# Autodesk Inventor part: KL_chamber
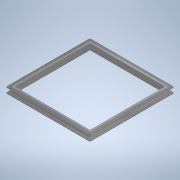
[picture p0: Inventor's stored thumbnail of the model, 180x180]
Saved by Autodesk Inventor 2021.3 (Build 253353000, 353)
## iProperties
Created: 2015-01
Part Number: KL_chamber
Material: アルミニウム 6061
Document SubType Name: Modeling
Designer: jh
Density: 2.71 g/cm^3
Appearance: アルミニウム - フラット
Mass: 47149.2 g
Surface Area: 21283 cm^2
Volume: 17398.2 cm^3
Author: jh
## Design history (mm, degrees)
sketch "Sketch4"
  geometry: L1 (-665, 665)-(665, 665); L2 (665, 665)-(665, -665); L3 (665, -665)-(-665, -665); L4 (-665, -665)-(-665, 665); L5 (-665, 665)-(665, -665); L6 (665, 665)-(-665, -665); 1 further point
  constraints: 12 end point, 2 midpoint, 2 parallel, 1 horizontal, 1 perpendicular
  dimensions: "d12" = 1330 distance of L2.end L3.end; "d13" = 1330 distance of L1.end L2.end
extrude "Extrusion4" new body sketch "Sketch4" distance "d14" = 10; taper "d15" = 0 deg
sketch "Sketch5"
  geometry: L1 (-592.75, 592.75)-(592.75, 592.75); L2 (592.75, 592.75)-(592.75, -592.75); L3 (592.75, -592.75)-(-592.75, -592.75); L4 (-592.75, -592.75)-(-592.75, 592.75); L5 (-592.75, 592.75)-(592.75, -592.75); L6 (592.75, 592.75)-(-592.75, -592.75); 1 further point
  constraints: 12 end point, 2 midpoint, 2 parallel, 1 horizontal, 1 perpendicular
  dimensions: "d16" = 1185.5 distance of L2.end L3.end; "d17" = 1185.5 distance of L1.end L2.end
extrude "Extrusion5" cut sketch "Sketch5" distance "d18" = 167.5; taper "d19" = 0 deg
sketch "Sketch6"
  geometry: L1 (-620, 620)-(620, 620); L2 (620, 620)-(620, -620); L3 (620, -620)-(-620, -620); L4 (-620, -620)-(-620, 620); L5 (-620, 620)-(620, -620); L6 (620, 620)-(-620, -620); 1 further point
  constraints: 12 end point, 2 midpoint, 2 parallel, 1 horizontal, 1 perpendicular
  dimensions: "d20" = 1240 distance of L2.end L3.end; "d21" = 1240 distance of L1.end L2.end
extrude "Extrusion6" join sketch "Sketch6" distance "d22" = 70; taper "d23" = 0 deg
sketch "Sketch7"
  geometry: L1 (-592.75, 592.75)-(592.75, 592.75); L2 (592.75, 592.75)-(592.75, -592.75); L3 (592.75, -592.75)-(-592.75, -592.75); L4 (-592.75, -592.75)-(-592.75, 592.75); L5 (-592.75, 592.75)-(592.75, -592.75); L6 (592.75, 592.75)-(-592.75, -592.75); 1 further point
  constraints: 12 end point, 2 midpoint, 2 parallel, 1 horizontal, 1 perpendicular
  dimensions: "d24" = 1185.5 distance of L2.end L3.end; "d25" = 1185.5 distance of L1.end L2.end
extrude "Extrusion7" cut sketch "Sketch7" distance "d26" = 445.75; taper "d27" = 0 deg
sketch "Sketch8"
  geometry: L1 (-665, 665)-(665, 665); L2 (665, 665)-(665, -665); L3 (665, -665)-(-665, -665); L4 (-665, -665)-(-665, 665); L5 (-665, 665)-(665, -665); L6 (665, 665)-(-665, -665); 1 further point
  constraints: 12 end point, 2 midpoint, 2 parallel, 1 horizontal, 1 perpendicular
  dimensions: "d28" = 1330 distance of L2.end L3.end; "d29" = 1330 distance of L1.end L2.end
extrude "Extrusion8" join sketch "Sketch8" distance "d30" = 10; taper "d31" = 0 deg
sketch "Sketch9"
  geometry: L1 (-592.75, 592.75)-(592.75, 592.75); L2 (592.75, 592.75)-(592.75, -592.75); L3 (592.75, -592.75)-(-592.75, -592.75); L4 (-592.75, -592.75)-(-592.75, 592.75); L5 (-592.75, 592.75)-(592.75, -592.75); L6 (592.75, 592.75)-(-592.75, -592.75); 1 further point
  constraints: 12 end point, 2 midpoint, 2 parallel, 1 horizontal, 1 perpendicular
  dimensions: "d32" = 1185.5 distance of L2.end L3.end; "d33" = 1185.5 distance of L1.end L2.end
extrude "Extrusion9" cut sketch "Sketch9" distance "d34" = 271.25; taper "d35" = 0 deg
sketch "Sketch10"
  geometry: L1 (-622.75, 622.75)-(622.75, 622.75); L2 (622.75, 622.75)-(622.75, -622.75); L3 (622.75, -622.75)-(-622.75, -622.75); L4 (-622.75, -622.75)-(-622.75, 622.75); L5 (-622.75, 622.75)-(622.75, -622.75); L6 (622.75, 622.75)-(-622.75, -622.75); 1 further point
  constraints: 12 end point, 2 midpoint, 2 parallel, 1 horizontal, 1 perpendicular
  dimensions: "d36" = 1245.5 distance of L2.end L3.end; "d37" = 1245.5 distance of L1.end L2.end
extrude "Extrusion10" join sketch "Sketch10" distance "d38" = 3; taper "d39" = 0 deg
sketch "Sketch11"
  geometry: L1 (-622.75, 622.75)-(622.75, 622.75); L2 (622.75, 622.75)-(622.75, -622.75); L3 (622.75, -622.75)-(-622.75, -622.75); L4 (-622.75, -622.75)-(-622.75, 622.75); L5 (-622.75, 622.75)-(622.75, -622.75); L6 (622.75, 622.75)-(-622.75, -622.75); 1 further point
  constraints: 12 end point, 2 midpoint, 2 parallel, 1 horizontal, 1 perpendicular
  dimensions: "d40" = 1245.5 distance of L2.end L3.end; "d41" = 1245.5 distance of L1.end L2.end
extrude "Extrusion11" join sketch "Sketch11" distance "d42" = 3; taper "d43" = 0 deg
sketch "Sketch12"
  geometry: L1 (-592.75, 592.75)-(592.75, 592.75); L2 (592.75, 592.75)-(592.75, -592.75); L3 (592.75, -592.75)-(-592.75, -592.75); L4 (-592.75, -592.75)-(-592.75, 592.75); L5 (-592.75, 592.75)-(592.75, -592.75); L6 (592.75, 592.75)-(-592.75, -592.75); 1 further point
  constraints: 12 end point, 2 midpoint, 2 parallel, 1 horizontal, 1 perpendicular
  dimensions: "d44" = 1185.5 distance of L2.end L3.end; "d45" = 1185.5 distance of L1.end L2.end
extrude "Extrusion12" cut sketch "Sketch12" distance "d46" = 429.25; taper "d47" = 0 deg
fillet "フィレット1" dims "d48" = 20
sketch "スケッチ13"
  geometry: L1 (665, -645)-(665, 645) reference; L2 (645, 665)-(-645, 665) reference; 3 further points
  dimensions: "d49" = 20 distance from line of L1 point (645, 645); "d50" = 20 distance from line of L2 point (645, 645); "d53" = 1290 distance of point (645, 645) point (-645, 645)
hole "穴1" sketch "スケッチ13" at (645, 645), (-645, 645) diameter "d59" = 6; stored, may be unused: countersink angle "d63" = 90 deg, drill point angle "d65" = 118 deg; dims "d60" = 100, "d61" = 4, "d62" = 2, "d64" = 100
sketch "スケッチ14"
  geometry: L1 (-645, -665)-(645, -665) reference; L2 (-665, 645)-(-665, -645) reference; 37 further points
  constraints: 1 horizontal, 1 vertical, 35 other
  dimensions: "d66" = 53 distance from line of L1 point (-650, -612); "d67" = 15 distance from line of L2 point (-650, -612); "d70" = 1300 distance of point (-650, -612) point (650, -612); "d73" = 72 distance of point (-650, -612) point (-650, -540)
hole "穴2" sketch "スケッチ14" diameter "d76" = 3.2; stored, may be unused: countersink angle "d80" = 90 deg, drill point angle "d82" = 118 deg; dims "d77" = 100, "d78" = 4, "d79" = 2, "d81" = 100
sketch "スケッチ15"
  geometry: L1 (-645, -665)-(645, -665) reference; L2 (-665, 645)-(-665, -645) reference; 37 further points
  constraints: 1 horizontal, 1 vertical, 35 other
  dimensions: "d83" = 15 distance from line of L1 point (-612, -650); "d84" = 53 distance from line of L2 point (-612, -650); "d87" = 72 distance of point (-612, -650) point (-540, -650); "d90" = 1300 distance of point (-612, -650) point (-612, 650)
hole "穴3" sketch "スケッチ15" diameter "d93" = 3.2; stored, may be unused: countersink angle "d97" = 90 deg, drill point angle "d99" = 118 deg; dims "d94" = 100, "d95" = 4, "d96" = 2, "d98" = 100
sketch "スケッチ17"
  geometry: L1 (-645, -665)-(645, -665) reference; L2 (-665, 645)-(-665, -645) reference; L3 (622.75, -622.75)-(-622.75, -622.75) reference; L4 (0, -622.75)-(0, -665); L5 (-645, -665)-(645, -665) reference; 5 further points
  constraints: 2 end point, 2 midpoint, 2 symmetric about line
  dimensions: "d104" = 15 distance from line of L1 point (-632, -650); "d105" = 33 distance from line of L2 point (-632, -650); "d106" = 40 distance of point (-592, -650) point (-632, -650); "d107" = 15 distance from line of L1 point (-592, -650)
hole "穴4" sketch "スケッチ17" at (-632, -650), (-592, -650), (632, -650), (592, -650) diameter "d108" = 5; stored, may be unused: countersink angle "d112" = 90 deg, drill point angle "d114" = 118 deg; dims "d109" = 100, "d110" = 4, "d111" = 2, "d113" = 100
body "Solid2"
